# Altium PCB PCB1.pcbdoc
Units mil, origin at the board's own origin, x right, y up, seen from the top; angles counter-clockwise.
Board outline 2908.74 x 1290 mil, 4 copper layers (Top Layer, Inner1, Inner2, Bottom Layer); 41 components, 33 nets, 166 pads, 81 vias.
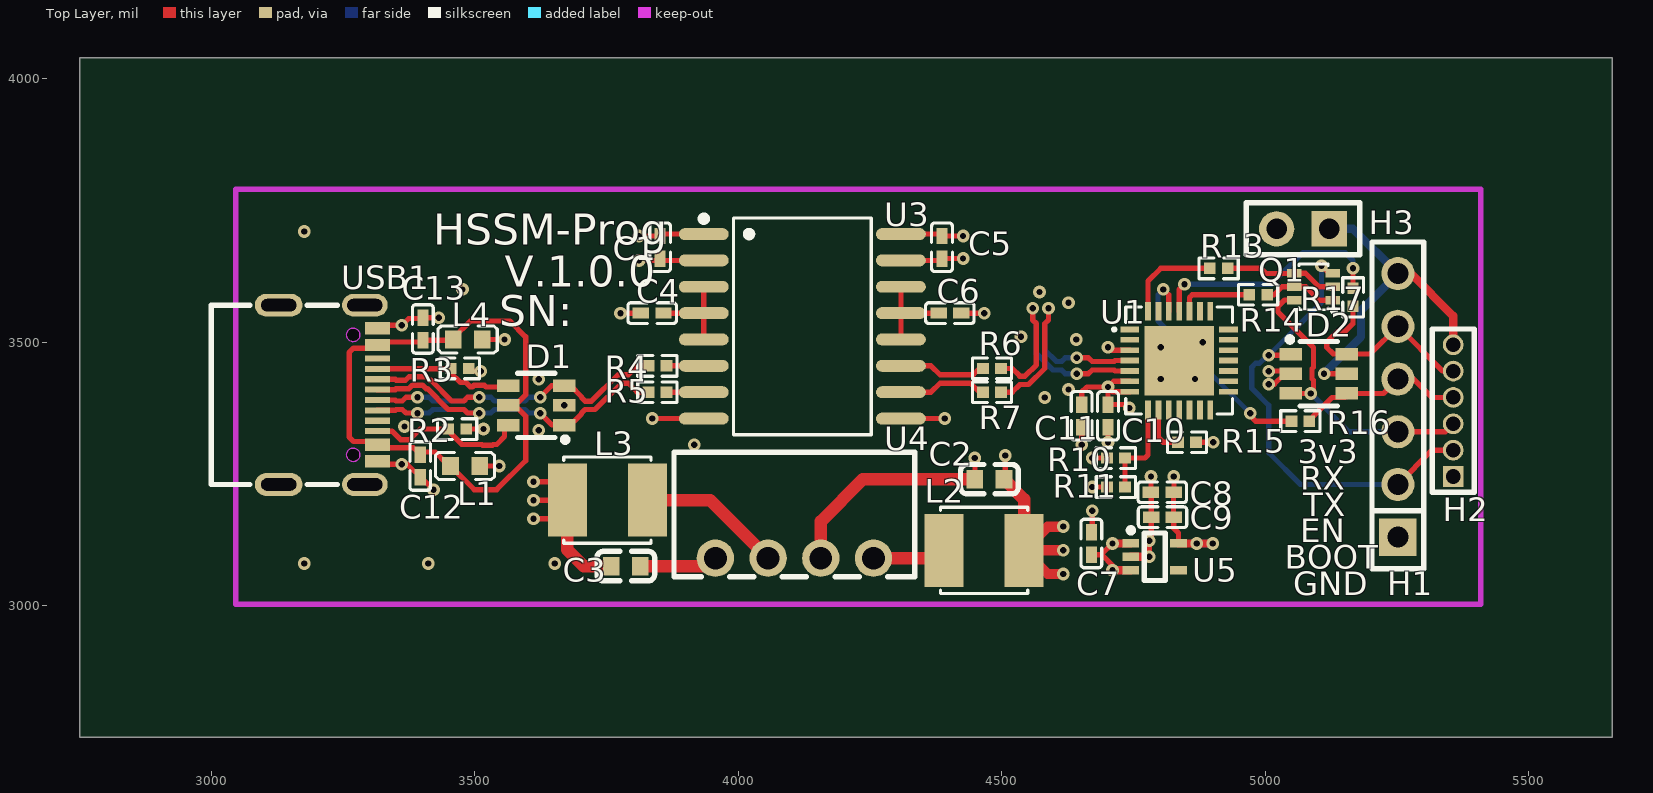
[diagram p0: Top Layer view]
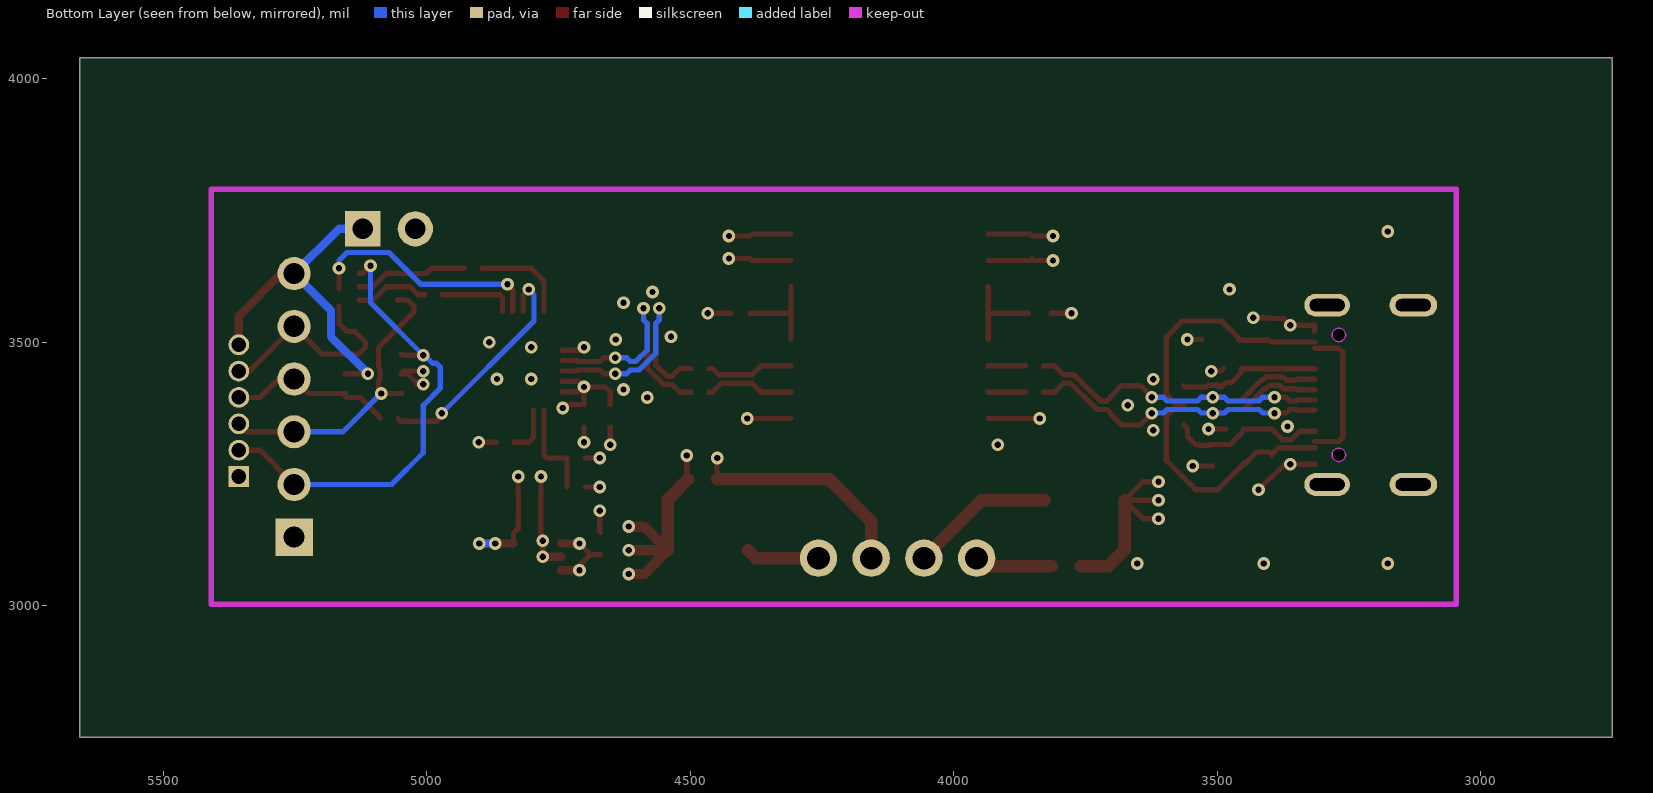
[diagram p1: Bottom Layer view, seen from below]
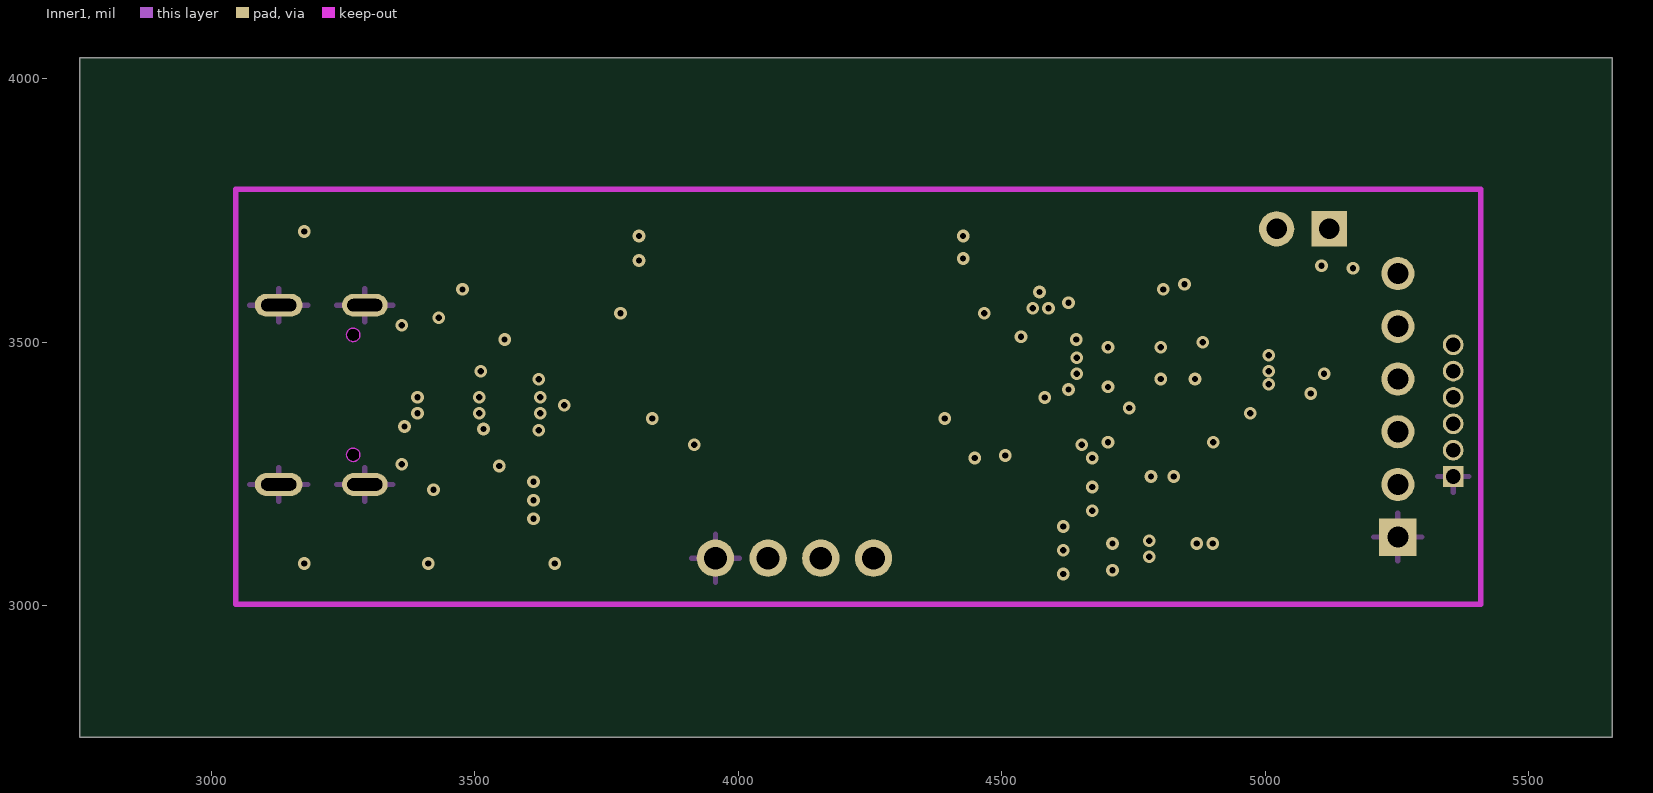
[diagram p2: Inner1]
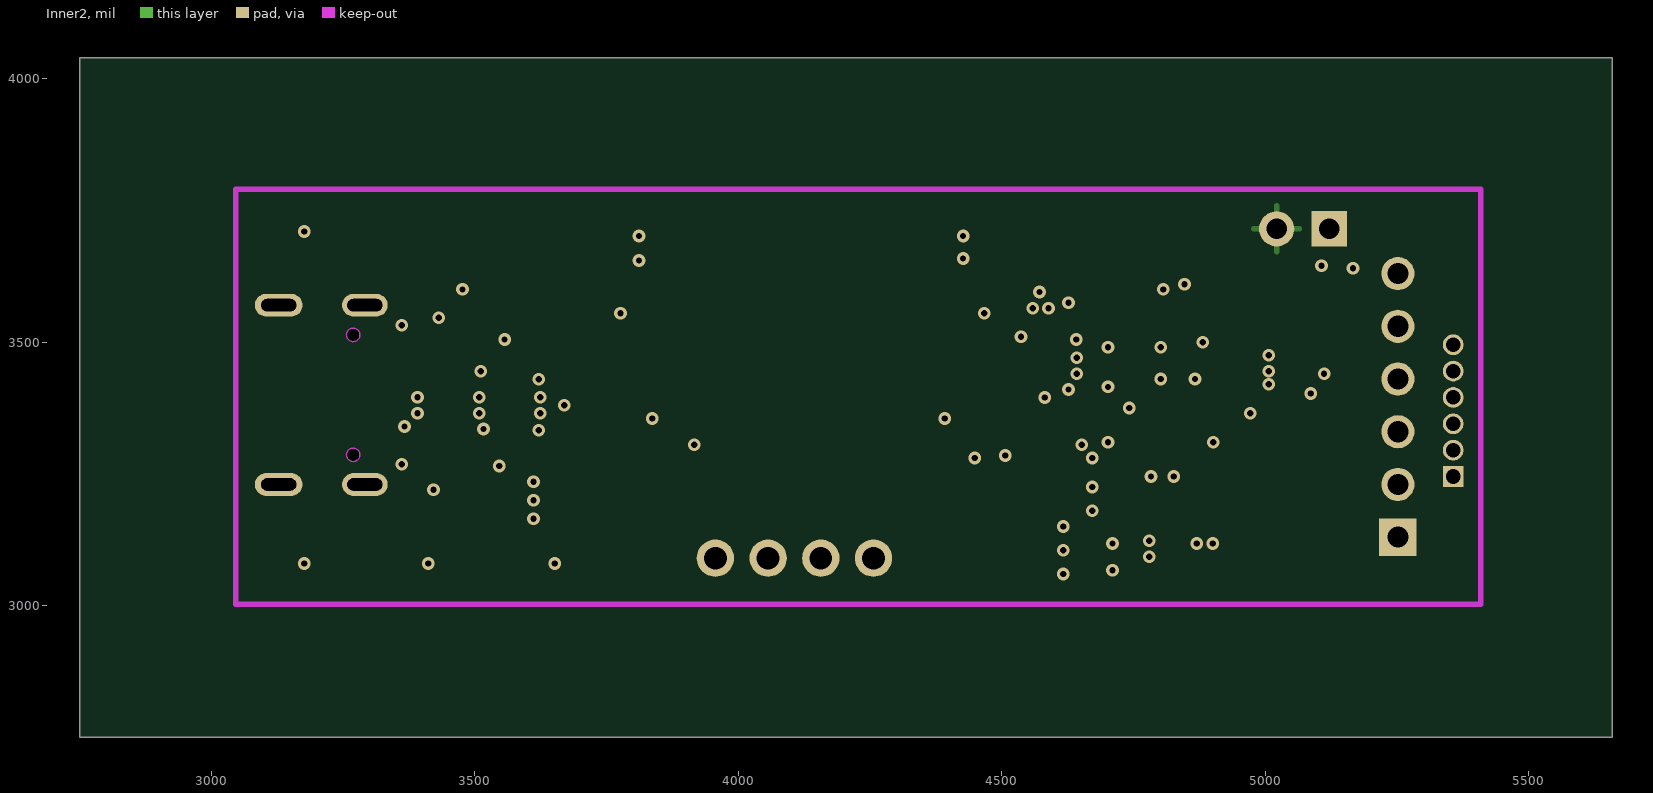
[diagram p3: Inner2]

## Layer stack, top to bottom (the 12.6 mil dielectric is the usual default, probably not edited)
Top Layer: signal copper (thickness not stored)
Dielectric: dielectric 12.6, FR-4, Dk 4.8
Inner1: signal copper (thickness not stored)
Dielectric: dielectric 12.6, FR-4, Dk 4.8
Inner2: signal copper (thickness not stored)
Dielectric: dielectric 12.6, FR-4, Dk 4.8
Bottom Layer: signal copper (thickness not stored)

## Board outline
5658.74,2750 2750,2750 2750,4040 5658.74,4040

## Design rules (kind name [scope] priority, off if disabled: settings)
BoardOutlineClearance copperThickness1oz [All] p0: genericclearance=10 ignorepadtopadclearanceinfootprint=FALSE except(0: Arc-SplitContinuation Track-SplitContinuation SMDPad-SplitContinuation THPad-SplitContinuation Via-SplitContinuation Fill-SplitContinuation Poly-SplitContinuation Region-SplitContinuation Text-SplitContinuation; 6: Track-CutoutEdge SMDPad-CutoutEdge THPad-CutoutEdge Via-CutoutEdge Region-CutoutEdge; 11.8: Track-OutlineEdge SMDPad-OutlineEdge THPad-OutlineEdge Via-OutlineEdge Fill-OutlineEdge Region-OutlineEdge Poly-OutlineEdge Text-OutlineEdge Fill-CutoutEdge)
BoardOutlineClearance copperThickness2oz [All] p0: genericclearance=10 ignorepadtopadclearanceinfootprint=FALSE except(0: Arc-SplitContinuation Track-SplitContinuation SMDPad-SplitContinuation THPad-SplitContinuation Via-SplitContinuation Fill-SplitContinuation Poly-SplitContinuation Region-SplitContinuation Text-SplitContinuation; 6: Track-CutoutEdge SMDPad-CutoutEdge THPad-CutoutEdge Via-CutoutEdge Region-CutoutEdge; 11.8: Track-OutlineEdge SMDPad-OutlineEdge THPad-OutlineEdge Via-OutlineEdge Fill-OutlineEdge Region-OutlineEdge Poly-OutlineEdge Text-OutlineEdge Fill-CutoutEdge)
Clearance copperThickness1oz [(InNet('VBUS') OR InNet('GND') OR InNet('ISOVBUS') OR InNet('ISOGND') OR InNet('VDD') OR InNet('ISOVDD') OR InNet('ISO3V3') OR InNet('USB_DN') OR InNet('USB_DP') OR InNet('CC2') OR InNet('CC1') OR InNet('ISO_EN') OR InNet('ISO_BOOT') OR InNet('ISO_RX') OR InNet('ISO_TX') OR InNet('$1N3534') OR InNet('$1N3529') OR InNet('DTR') OR InNet('RTS') OR InNet('ISO_USB_DN') OR InNet('ISO_USB_DP') OR InNet('$1N4589') OR InNet('$1N5325') OR InNet('$1N5370') OR InNet('$1N4087') OR InNet('$1N8654') OR InNet('$1N8663') OR InNet('VBUS_CONN') OR InNet('USB_DN_IC') OR InNet('USB_DP_IC') OR InNet('ISO_USB_DN_IC') OR InNet('ISO_USB_DP_IC') OR InNet('3V3_OUT'))] p1: gap=7 ignorepadtopadclearanceinfootprint=FALSE except(4: Track-Track; 6: Track-SMDPad SMDPad-SMDPad Track-THPad SMDPad-THPad THPad-THPad Track-Via SMDPad-Via THPad-Via Via-Via SMDPad-Fill THPad-Fill Via-Fill Fill-Fill Track-Region SMDPad-Region THPad-Region Via-Region Region-Region Track-Poly SMDPad-Poly THPad-Poly Via-Poly Fill-Poly Region-Poly Poly-Poly Track-Text SMDPad-Text THPad-Text Via-Text Fill-Text Region-Text Poly-Text Text-Text; 6.9: Track-Hole SMDPad-Hole THPad-Hole Via-Hole Fill-Hole Region-Hole Poly-Hole Text-Hole Sheet-Hole; 11.8: Track-Fill Fill-Region Track-Sheet SMDPad-Sheet THPad-Sheet Via-Sheet Fill-Sheet Region-Sheet Poly-Sheet Text-Sheet)
Clearance copperThickness2oz [All] p1: gap=7 ignorepadtopadclearanceinfootprint=FALSE except(6: Track-SMDPad SMDPad-SMDPad Track-THPad SMDPad-THPad THPad-THPad Track-Via SMDPad-Via THPad-Via Via-Via SMDPad-Fill THPad-Fill Via-Fill Fill-Fill Track-Region SMDPad-Region THPad-Region Via-Region Region-Region Track-Poly SMDPad-Poly THPad-Poly Via-Poly Fill-Poly Region-Poly Poly-Poly Track-Text SMDPad-Text THPad-Text Via-Text Fill-Text Region-Text Poly-Text Text-Text; 6.9: Track-Hole SMDPad-Hole THPad-Hole Via-Hole Fill-Hole Region-Hole Poly-Hole Text-Hole Sheet-Hole; 8: Track-Track; 11.8: Track-Fill Fill-Region Track-Sheet SMDPad-Sheet THPad-Sheet Via-Sheet Fill-Sheet Region-Sheet Poly-Sheet Text-Sheet)
DiffPairsRouting differentialPair [All] p1: maxuncoupledlength=10 minlimit=5.9843 maxlimit=5.9843 mostfreqgap=5.9843 toplayer_minwidth=5 toplayer_prefwidth=10 toplayer_maxwidth=100 bottomlayer_minwidth=5 bottomlayer_prefwidth=10 bottomlayer_maxwidth=100 midlayer1_minwidth=5 midlayer1_prefwidth=10 midlayer1_maxwidth=100 midlayer2_minwidth=5 midlayer2_prefwidth=10 midlayer2_maxwidth=100
PasteMaskExpansion pasteMaskExpansion [All] p1: expansion=0
PlaneConnect innerPlane [All] p1: planeconnectstyle=Relief reliefexpansion=20 reliefentries=4 reliefconductorwidth=10 reliefairgap=10
PolygonConnect copperRegion [All] p1: connectstyle=Relief reliefentries=4 reliefconductorwidth=10 polygonreliefangle="90 Angle" airgapwidth=10
RoutingVias viaSize [All] p1: viastyle="Through Hole" holewidth=12.0078 minholewidth=11.811 maxholewidth=248.0314 width=24.0158 minwidth=19.685 maxwidth=393.7008
SolderMaskExpansion solderMaskExpansion [All] p1: useseparateexpansions=TRUE expansion=2.0079 expansionbottom=2.0079
Width copperThickness1oz [All] p1: maxlimit=100 minlimit=5 preferedwidth=10
Width copperThickness2oz [All] p1: maxlimit=100 minlimit=8 preferedwidth=10

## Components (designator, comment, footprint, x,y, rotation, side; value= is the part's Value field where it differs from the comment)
C1 "" C0402 3851.54,3680 r90 top
C2 "" C0603 4476.54,3240 r0 top
C3 "" C0603 3786.54,3075 r180 top
C4 "" C0402 3836.54,3555 r0 top
C5 "" C0402 4386.54,3680 r90 top
C6 "" C0402 4401.54,3555 r180 top
C7 "" C0402 4670.04,3117.88 r270 top
C8 "" C0402 4804.46,3215 r0 top
C9 "" C0402 4805.04,3167.88 r0 top
C10 "" C0402 4701.54,3360 r90 top
C11 "" C0402 4651.54,3360 r90 top
C12 "" C0402 3396.54,3265 r90 top
C13 "" C0402 3401.54,3525 r270 top
D1 "" SOT-23-6_L2.9-W1.6-P0.95-LS2.8-BR 3616.54,3380 r0 top
D2 "" SOT-23-6_L2.9-W1.6-P0.95-LS2.8-BR 5101.54,3440 r180 top
H1 "" HDR-TH_6P-P2.54-V-F 5251.54,3380 r90 top
H2 "" HDR-TH_6P-P1.27-V-M-A 5356.54,3370 r90 top
H3 "" HDR-TH_2P-P2.54-V-F 5071.54,3715 r180 top
L1 "" L0603 3481.54,3265 r0 top
L2 "" IND-SMD_L4.0-W4.0_SMNR4020 4466.54,3105 r0 top
L3 "" IND-SMD_L4.0-W4.0_SMNR4020 3751.54,3200 r0 top
L4 "" L0603 3486.54,3505 r0 top
Q1 "" SOT-363_L2.0-W1.3-P0.65-LS2.1-TL 5091.54,3605 r180 top
R2 "" R0402 3466.54,3335 r180 top
R3 "" R0402 3471.54,3450 r180 top
R4 "" R0402 3846.54,3455 r0 top
R5 "" R0402 3846.54,3405 r0 top
R6 "" R0402 4481.54,3450 r0 top
R7 "" R0402 4481.54,3405 r0 top
R10 "" R0402 4716.54,3280 r180 top
R11 "" R0402 4716.54,3225 r0 top
R13 "" R0402 4911.54,3640 r180 top
R14 "" R0402 4986.54,3590 r180 top
R15 "" R0402 4851.54,3310 r180 top
R16 "" R0402 5066.54,3350 r0 top
R17 "" R0402 5166.54,3585 r270 top
U1 "" QFN-28_L5.0-W5.0-P0.50-TL-EP3.3 4836.54,3465 r0 top
U3 "" SOIC-16_L10.3-W7.5-P1.27-LS10.3-BL 4121.54,3530 r270 top
U4 "" PWRM-TH_HLK-1DXXXX 4106.54,3090 r180 top
U5 "" SOT-353_L2.1-W1.3-P0.65-LS2.3-BL 4790.04,3092.88 r270 top
USB1 "" USB-C_UC09-0B16F00P11 3221.54,3400 r270 top

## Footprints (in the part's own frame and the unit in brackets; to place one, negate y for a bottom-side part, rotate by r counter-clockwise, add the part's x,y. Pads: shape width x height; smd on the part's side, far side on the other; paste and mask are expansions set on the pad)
C0402 [mm]
  rect 0.79x0.54 smd: 1(-0.545,0) 2(0.545,0)
  silkscreen extent -1.17,-0.5 1.17,0.5
C0603 [mm]
  rect 0.8x0.9 smd: 1(-0.7,0) 2(0.7,0)
  silkscreen extent -1.39,-0.71 1.39,0.71
HDR-TH_2P-P2.54-V-F [mm]
  rect 1.7x1.7 hole 1: 1(-1.27,0)
  round 1.7 hole 1: 2(1.27,0)
  silkscreen extent -2.74,-1.25 2.74,1.25
HDR-TH_6P-P1.27-V-M-A [mm]
  rect 1x1 hole 0.7: 1(-3.175,0)
  round 1 hole 0.7: 2(-1.905,0) 3(-0.635,0) 4(0.635,0) 5(1.905,0) 6(3.175,0)
  silkscreen extent -3.94,-1.02 3.94,1.02
HDR-TH_6P-P2.54-V-F [mm]
  rect 1.8x1.8 hole 1.02: 1(-6.35,0)
  round 1.6 hole 1.02: 2(-3.81,0) 3(-1.27,0) 4(1.27,0) 5(3.81,0) 6(6.35,0)
  silkscreen extent -7.87,-1.25 7.87,1.25
IND-SMD_L4.0-W4.0_SMNR4020 [mm]
  rect 1.874x3.52 smd: 1(1.928,0) 2(-1.928,0)
  silkscreen extent -2.1,-2.08 2.1,2.08
L0603 [mm]
  rect 0.8x0.864 smd: 1(-0.7,0) 2(0.7,0)
  silkscreen extent -1.42,-0.65 1.42,0.65
PWRM-TH_HLK-1DXXXX [mm]
  round 1.8 hole 1.1: 1(3.81,0) 2(1.27,0) 3(-1.27,0) 4(-3.81,0)
  silkscreen extent -5.8,-5.1 5.8,0.9
QFN-28_L5.0-W5.0-P0.50-TL-EP3.3 [mm]
  rect 0.905x0.28 smd: 1(-2.377,1.5) 2(-2.377,1) 3(-2.377,0.5) 4(-2.377,0) 5(-2.377,-0.5) 6(-2.377,-1) 7(-2.377,-1.5) 15(2.377,-1.5) 16(2.377,-1) 17(2.377,-0.5) 18(2.377,0) 19(2.377,0.5) 20(2.377,1) 21(2.377,1.5)
  rect 0.28x0.905 smd: 8(-1.5,-2.377) 9(-1,-2.377) 10(-0.5,-2.377) 11(0,-2.377) 12(0.5,-2.377) 13(1,-2.377) 14(1.5,-2.377) 22(1.5,2.377) 23(1,2.377) 24(0.5,2.377) 25(0,2.377) 26(-0.5,2.377) 27(-1,2.377) 28(-1.5,2.377)
  rect 3.35x3.35 smd: 29(0,0)
  silkscreen extent -3.2,-2.58 2.58,2.58
R0402 [mm]
  rect 0.566x0.54 smd: 1(-0.433,0) 2(0.433,0)
  silkscreen extent -0.94,-0.5 0.94,0.5
SOIC-16_L10.3-W7.5-P1.27-LS10.3-BL [mil]
  oval 22.6x94.51 smd: 1(-175,-187.02) 2(-125,-187.02) 3(-75,-187.02) 4(-25,-187.02) 5(25,-187.02) 6(75,-187.02) 7(125,-187.02) 8(175,-187.02) 9(175,187.02) 10(125,187.02) 11(75,187.02) 12(25,187.02) 13(-25,187.02) 14(-75,187.02) 15(-125,187.02) 16(-175,187.02)
  silkscreen extent -210,-193 206,131
SOT-23-6_L2.9-W1.6-P0.95-LS2.8-BR [mm]
  rect 1.1x0.6 smd: 1(1.35,-0.95) 2(1.35,0) 3(1.35,0.95) 4(-1.35,0.95) 5(-1.35,0) 6(-1.35,-0.95)
  silkscreen extent -0.9,-1.78 1.52,1.55
SOT-353_L2.1-W1.3-P0.65-LS2.3-BL [mm]
  rect 0.4x0.8 smd: 1(-0.65,-1.15) 2(0,-1.15) 3(0.65,-1.15) 4(0.65,1.15) 5(-0.65,1.15)
  silkscreen extent -1.4,-1.27 1.14,0.51
SOT-363_L2.0-W1.3-P0.65-LS2.1-TL [mm]
  rect 0.7x0.42 smd: 1(-0.92,0.65) 2(-0.92,0) 3(-0.92,-0.65) 4(0.92,-0.65) 5(0.92,0) 6(0.92,0.65)
  silkscreen extent -1.09,-1.1 0.7,1.24
USB-C_UC09-0B16F00P11 [mm]
  oval 1.1x2.2 hole 0.6 slot 1.7 at 90 deg: 17(4.32,1.772) 20(-4.32,1.772)
  oval 1.1x2.3 hole 0.6 slot 1.7 at 90 deg: 18(4.32,-2.377) 19(-4.32,-2.378)
  rect 0.3x1.21 smd: A1(-3.35,2.378) A4(-2.55,2.378) A5(-1.25,2.378) A6(-0.25,2.378) A7(0.25,2.378) A8(1.249,2.378) A9(2.55,2.378) A12(3.35,2.378) B1(3.05,2.378) B4(2.25,2.378) B5(1.75,2.378) B6(0.75,2.378) B7(-0.75,2.378) B8(-1.75,2.378) B9(-2.25,2.378) B12(-3.05,2.378)
  Board Outline Layer circle w0.005: c2.89,1.212 r0.325
  Board Outline Layer circle w0.005: c-2.89,1.212 r0.325
  Board Outline Layer region: 2.89,1.537 3.031,1.505 3.144,1.415 3.207,1.285 3.207,1.14 3.144,1.01 3.031,0.92 2.89,0.887 2.89,0.887 2.749,0.92 2.636,1.01 2.573,1.14 2.573,1.285 2.636,1.415 2.749,1.505 2.89,1.537
  Board Outline Layer region: -2.89,1.537 -2.749,1.505 -2.636,1.415 -2.573,1.285 -2.573,1.14 -2.636,1.01 -2.749,0.92 -2.89,0.887 -2.89,0.887 -3.031,0.92 -3.144,1.01 -3.207,1.14 -3.207,1.285 -3.144,1.415 -3.031,1.505 -2.89,1.537
  Multi-Layer board cut-out: 2.89,1.537 3.031,1.505 3.144,1.415 3.207,1.285 3.207,1.14 3.144,1.01 3.031,0.92 2.89,0.887 2.89,0.887 2.749,0.92 2.636,1.01 2.573,1.14 2.573,1.285 2.636,1.415 2.749,1.505 2.89,1.537
  Multi-Layer board cut-out: -2.89,1.537 -2.749,1.505 -2.636,1.415 -2.573,1.285 -2.573,1.14 -2.636,1.01 -2.749,0.92 -2.89,0.887 -2.89,0.887 -3.031,0.92 -3.144,1.01 -3.207,1.14 -3.207,1.285 -3.144,1.415 -3.031,1.505 -2.89,1.537
  silkscreen extent -4.32,-5.63 4.32,0.44

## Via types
v1: diameter 24.02, hole 12.01, Top Layer to Bottom Layer, 81 vias

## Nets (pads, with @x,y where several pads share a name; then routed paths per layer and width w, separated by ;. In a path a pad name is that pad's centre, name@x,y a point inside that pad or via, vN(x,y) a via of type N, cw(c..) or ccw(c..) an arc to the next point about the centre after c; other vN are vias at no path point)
3V3_OUT: D2.5 H1.6 H2.6 H3.1 | length 649.5
  Top Layer w10: v1(5111.54,3440) D2.5
  Top Layer w15.75: H1.6 5276.54,3630 5356.54,3550 H2.6
  Bottom Layer w15.75: v1(5111.54,3440) 5181.54,3510 5181.54,3560 H1.6 5166.54,3715 H3.1
$1N3529: L3.1 U4.2 | length 274.7
  Top Layer w23.62: L3.1 3946.53,3200 U4.2
$1N3534: L2.2 U4.4 | length 140.3
  Top Layer w23.62: U4.4 4375.62,3090 L2.2
$1N4087: R15.2 U1.9 | length 93.2
  Top Layer w10: U1.9 4797.17,3319.37 4806.54,3310 R15.2
$1N4589: R10.1 R11.2 U1.8 | length 186.8
  Top Layer w10: R11.2 R10.1 4771.54,3280 4777.49,3285.95 U1.8
$1N5325: R13.2 U1.28 | length 184.3
  Top Layer w10: U1.28 4777.49,3615.95 4801.54,3640 R13.2
$1N5370: R14.2 U1.24 | length 141.6
  Top Layer w10: U1.24 4856.23,3584.69 4861.54,3590 R14.2
$1N8654: R17.1 U1.25 | length 459.6
  Top Layer w10: U1.25 4836.54,3600 v1(4846.54,3610) ; R17.1 v1(5166.54,3640)
  Bottom Layer w10: v1(4846.54,3610) 5011.54,3610 5071.54,3670 5151.54,3670 5166.54,3655 v1(5166.54,3640)
$1N8663: R16.1 U1.26 | length 451.5
  Top Layer w10: v1(4806.54,3600) 4816.86,3589.68 U1.26 ; v1(4971.54,3365) 4971.54,3360 4981.54,3350 R16.1 R16.1@5054.5,3355
  Bottom Layer w10: v1(4806.54,3600) 4796.54,3590 4796.54,3540 v1(4971.54,3365)
CC1: D1.4 R3.2 USB1.A5 | length 265.5
  Top Layer w10: USB1.A5 R3.2@3448.71,3449.22 ; R3.2 3454.5,3441.78 3472.89,3423.39 3483.15,3423.39 3491.54,3415 3495.44,3415 3498.73,3418.28 3517.77,3418.28 3521.06,3415 3560.99,3415 D1.4
CC2: D1.6 R2.2 USB1.B5 | length 293
  Top Layer w10: USB1.B5 3342.91,3331.11 3359.02,3315 3376.54,3315 3396.54,3335 R2.2 ; R2.2@3453.78,3327.5 3475.39,3305.89 3513.13,3305.89 3514.51,3304.51 3533.56,3304.51 3534.94,3305.89 3541.67,3305.89 3556.54,3320.75 3556.54,3335.75 D1.6
DTR: Q1.2 Q1.4 R13.1 | length 214.2
  Top Layer w10: R13.1 4991.54,3640 5001.54,3630 5054.73,3630 Q1.4 5075.95,3630.59 5101.54,3605 Q1.2
GND: C1.1 C3.1 C4.1 C12.1 C13.1 D1.2 R2.1 R3.1 U3.2 U3.8 U4.1 USB1.17 USB1.18 USB1.19 USB1.20 USB1.A1 USB1.A12 USB1.B1 USB1.B12 | length 729.6
  Top Layer w10: USB1.A12 v1(3361.54,3268.12) 3371.96,3268.12 C12.1 3398,3243.54 v1(3421.54,3220) ; USB1.B12 USB1.A1 v1(3361.54,3531.9) 3374.64,3545 3400.08,3545 C13.1 v1(3431.54,3546.46) ; R2.1 v1(3516.54,3335) ; R3.1 3493.58,3445 v1(3511.54,3445) ; v1(3776.54,3555) C4.1 ; v1(3811.54,3655) 3848,3655 C1.1 3855.08,3655 U3.2 ; v1(3836.54,3355) U3.8
  Top Layer w23.62: C3.1 3941.54,3075 U4.1
  other v1: 3176.54,3080 3411.54,3080 3651.54,3080 3916.54,3305 3621.54,3332.54 3366.54,3340 3669.69,3380 3621.54,3429.51 3476.54,3600 3176.54,3710
ISO3V3: C8.2 C9.2 C10.2 C11.2 H3.2 R15.1 U1.6 U1.7 U5.5 | length 498.5
  Top Layer w10: C11.2 4651.54,3405 4661.54,3415 v1(4701.54,3415) ; v1(4741.54,3375) 4735.08,3381.46 C10.2 v1(4701.54,3415) ; U1.7 4710.6,3405.94 v1(4701.54,3415) ; U1.6 4712.17,3425.63 v1(4701.54,3415) ; C9.2@4826.5,3162.88 4826.5,3146.42 4835.31,3137.6 U5.5 ; C9.2 4825.92,3168.46 C8.2 4826.54,3215.62 v1(4826.54,3245) ; R15.1 v1(4901.54,3310)
  Top Layer w15.75: U5.5 4835.9,3117.88 v1(4870.04,3117.88) v1(4900.04,3117.88)
  Bottom Layer w15.75: v1(4870.04,3117.88) v1(4900.04,3117.88)
ISO_BOOT: D2.1 H1.2 H2.2 Q1.3 | length 900.7
  Top Layer w10: v1(5006.54,3475) 5045.99,3475 D2.1 ; v1(5106.54,3645) 5120.95,3630.59 Q1.3 ; H1.2 5316.54,3295 H2.2
  Bottom Layer w10: v1(5106.54,3645) 5106.54,3575 v1(5006.54,3475) 4999.53,3467.99 4997.01,3467.99 4989.02,3460 4981.54,3460 4974.46,3452.93 4974.46,3412.07 5006.54,3380 5006.54,3290 5066.54,3230 H1.2
ISO_EN: D2.3 H1.3 H2.3 Q1.6 | length 578.5
  Top Layer w10: D2.3 v1(5086.54,3402.6) 5091.54,3407.6 5091.54,3427.48 5088.54,3430.48 5088.54,3449.52 5091.54,3452.52 5091.54,3490 5024.04,3557.5 5024.04,3567.5 5036.54,3580 5054.73,3580 Q1.6 ; H1.3 5341.54,3330 H2.3
  Bottom Layer w10: v1(5086.54,3402.6) 5159.14,3330 H1.3
ISO_RX: D2.6 H1.5 H2.5 R17.2 | length 409.7
  Top Layer w10: R17.2 5166.54,3535 5151.54,3520 5136.54,3520 5116.54,3500 5116.54,3490 5129.14,3477.4 D2.6 5198.94,3477.4 H1.5 5336.54,3445 H2.5
ISO_TX: D2.4 H1.4 H2.4 R16.2 | length 317.6
  Top Layer w10: R16.2@5088.58,3355 5088.58,3357.04 5126.54,3395 5152.09,3395 5154.69,3397.6 D2.4 5224.14,3402.6 H1.4 5281.54,3430 5316.54,3395 H2.4
ISO_USB_DN: R6.2 U1.5 | length 477.3
  Top Layer w10: R6.2 4519.71,3450 4534.22,3435.49 4544.22,3435.49 4565.55,3456.82 4565.55,3535 4558.54,3542.01 v1(4558.54,3564.02) ; v1(4642.52,3440.16) 4664.53,3440.16 4671.54,3447.16 4713.27,3447.16 4715.12,3445.31 U1.5
  Bottom Layer w10: v1(4558.54,3564.02) 4558.54,3542.01 4565.55,3535 4565.55,3478.49 4596.88,3447.16 4613.5,3447.16 4620.51,3440.16 v1(4642.52,3440.16)
ISO_USB_DN_IC: R6.1 U3.11 | length 168
  Top Layer w10: U3.11 4365.81,3455 4382.82,3437.99 4445.87,3437.99 4457.88,3450 R6.1
ISO_USB_DP: R7.2 U1.4 | length 477.3
  Top Layer w10: R7.2 4519.71,3405 4534.22,3419.51 4550.84,3419.51 4581.54,3450.2 4581.54,3535 4588.54,3542.01 v1(4588.54,3564.02) ; v1(4642.52,3470.16) 4664.53,3470.16 4671.54,3463.15 4713.27,3463.15 4715.12,3465 U1.4
  Bottom Layer w10: v1(4588.54,3564.02) 4588.54,3542.01 4581.54,3535 4581.54,3485.12 4603.5,3463.15 4613.5,3463.15 4620.51,3470.16 v1(4642.52,3470.16)
ISO_USB_DP_IC: R7.1 U3.10 | length 170
  Top Layer w10: U3.10 4365.81,3405 4382.82,3422.01 4440.87,3422.01 4457.88,3405 R7.1
ISOGND: C2.1 C5.1 C6.1 C7.1 C8.1 C9.1 C10.1 C11.1 D2.2 H1.1 H2.1 R11.1 U1.3 U1.29 U3.9 U3.15 U4.3 U5.2 | length 1134.6
  Top Layer w10: U3.9 v1(4391.54,3355) ; U3.15 4383,3655 C5.1 v1(4426.54,3658.54) ; C6.1 v1(4466.54,3555) ; C2.1 v1(4448.98,3280) ; v1(4651.54,3305) C11.1 ; C7.1 4671.54,3140.84 v1(4671.54,3180) ; v1(4671.54,3225) R11.1 ; v1(4701.54,3310) C10.1 ; v1(4701.54,3490) 4706.86,3484.68 U1.3 ; v1(4780.04,3092.88) v1(4780.04,3122.88) 4783.58,3126.42 C9.1@4783.58,3162.88 ; v1(4783,3245) C8.1 4783.58,3214.42 C9.1 ; v1(5006.54,3420) 5016.79,3420 5036.79,3440 D2.2 5043.39,3445 v1(5006.54,3445)
  Top Layer w15.75: U5.2 v1(4780.04,3092.88)
  Top Layer w23.62: U4.3 4156.54,3160 4236.54,3240 C2.1
  other v1: 4581.54,3395 4626.54,3410 4801.54,3430 4866.54,3430 4801.54,3490 4881.54,3500 4641.54,3505 4536.54,3510 4626.54,3575 4571.54,3595
ISOVBUS: C2.2 C5.2 C7.2 L2.1 R10.2 U3.16 U5.1 U5.3 | length 761.3
  Top Layer w10: U3.16 4383,3705 C5.2 v1(4426.54,3701.46) ; C2.2 4506.54,3242.44 v1(4506.54,3285) ; C7.2 4688.58,3096.42 ; v1(4671.54,3280) R10.2 ; v1(4710.04,3067.29) 4710.04,3076.4 4690.02,3096.42 4688.58,3096.42 ; v1(4710.04,3117.88) 4688.58,3096.42
  Top Layer w15.75: v1(4710.04,3067.29) U5.3 ; v1(4710.04,3117.88) 4744.17,3117.88 U5.1
  Top Layer w19.68: v1(4616.54,3060) 4587.45,3060 L2.1 ; v1(4616.54,3105) L2.1 ; v1(4616.54,3150) 4587.45,3150 L2.1
  Top Layer w23.62: C2.2 4542.45,3201.65 L2.1
ISOVDD: C6.2 U3.12 U3.13 U3.14 | length 178.6
  Top Layer w10: U3.12 U3.13 ; U3.14 U3.13 ; C6.2@4386.54,3553.54 4385.08,3555 U3.13
RTS: Q1.1 Q1.5 R14.1 | length 141
  Top Layer w10: R14.1 5016.54,3590 5031.54,3605 Q1.5 5076.54,3605 5102.13,3579.41 Q1.1
USB_DN: D1.3 R4.1 USB1.A7 USB1.B7 | length 798.3
  Top Layer w10: USB1.A7 3348.96,3390.17 3350.81,3388.32 3362.36,3388.32 3369.37,3395.32 v1(3391.38,3395.32) ; USB1.B7 3348.96,3429.54 3350.81,3427.69 3368.62,3427.69 3375.23,3434.3 3407.52,3434.3 3414.14,3427.69 3416.68,3427.69 3456.08,3388.28 3479.23,3388.28 3486.24,3395.29 v1(3508.25,3395.29) ; v1(3624.03,3395.29) 3646.14,3417.4 D1.3 3681.28,3417.4 3702.32,3396.36 3702.32,3394.76 3709.09,3387.99 3721.54,3387.99 3771.54,3437.99 3791.35,3437.99 3808.36,3455 R4.1
  Bottom Layer w10: v1(3391.38,3395.32) 3413.39,3395.32 3420.4,3388.32 3479.23,3388.28 3486.24,3395.29 v1(3508.25,3395.29) 3530.26,3395.29 3537.27,3388.28 3595.01,3388.28 3602.02,3395.29 v1(3624.03,3395.29)
USB_DN_IC: R4.2 U3.6 | length 70.9
  Top Layer w10: R4.2 U3.6
USB_DP: D1.1 R5.1 USB1.A6 USB1.B6 | length 798.5
  Top Layer w10: USB1.B6 3348.96,3370.48 3350.81,3372.33 3362.36,3372.33 3369.37,3365.32 v1(3391.38,3365.32) ; USB1.A6 3348.96,3409.85 3350.81,3411.7 3375.24,3411.7 3381.86,3418.32 3400.9,3418.32 3407.52,3411.7 3410.06,3411.7 3449.46,3372.3 3479.23,3372.3 3486.24,3365.29 v1(3508.25,3365.29) ; v1(3624.03,3365.29) 3646.72,3342.6 D1.1 3681.28,3342.6 3702.32,3363.64 3702.32,3365.24 3709.09,3372.01 3728.16,3372.01 3778.16,3422.01 3791.35,3422.01 3808.36,3405 R5.1
  Bottom Layer w10: v1(3391.38,3365.32) 3413.39,3365.32 3420.4,3372.33 3479.23,3372.3 3486.24,3365.29 v1(3508.25,3365.29) 3530.26,3365.29 3537.27,3372.3 3595.01,3372.3 3602.02,3365.29 v1(3624.03,3365.29)
USB_DP_IC: R5.2 U3.7 | length 70.9
  Top Layer w10: R5.2 U3.7
VBUS: C1.2 C3.2 L1.2 L3.2 L4.2 U3.1 | length 600.8
  Top Layer w10: L1.2 v1(3546.54,3265) ; L4.2@3529.09,3505 v1(3556.54,3505) ; v1(3611.54,3165) 3640.63,3165 L3.2 ; v1(3611.54,3200) L3.2 ; v1(3611.54,3235) 3640.63,3235 L3.2 ; v1(3811.54,3701.46) C1.2 3855.08,3705 U3.1
  Top Layer w23.62: L3.2 3675.63,3105.91 3706.54,3075 C3.2
VBUS_CONN: C12.2 C13.2 D1.5 L1.1 L4.1 USB1.A4 USB1.A9 USB1.B4 USB1.B9 | length 1192
  Top Layer w10: USB1.A9 3383.39,3299.61 C12.2 3401.54,3291.46 3425.08,3291.46 3446.54,3270 3448.98,3270 L1.1 3498.98,3220 3541.54,3220 3596.54,3275 3596.54,3360 D1.5@3576.54,3380 ; USB1.B4 3270.11,3311.43 3261.54,3320 3261.54,3480 3270.12,3488.59 USB1.B9 ; USB1.A4 3398.39,3500.4 C13.2 3457.52,3503.54 L4.1 3458.98,3507.45 3491.54,3540 3566.54,3540 3596.54,3510 3596.54,3400 D1.5@3576.54,3380 ; D1.5 D1.5@3576.54,3380
VDD: C4.2 U3.3 U3.4 U3.5 | length 176.5
  Top Layer w10: C4.2 U3.4 ; U3.5 U3.4 ; U3.3 U3.4
pads on no net: U1.1 U1.2 U1.10 U1.11 U1.12 U1.13 U1.14 U1.15 U1.16 U1.17 U1.18 U1.19 U1.20 U1.21 U1.22 U1.23 U1.27 U5.4 USB1.A8 USB1.B8

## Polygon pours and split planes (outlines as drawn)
VBUS on Inner2 (solid, remove dead copper): 3046.54,3790 4023.29,3790 4023.29,3002.6 3046.54,3002.6
GND on Inner2 (solid, remove dead copper): 3336.54,3460 3686.54,3460 3686.54,3310 3336.54,3310
GND on Inner1 (solid, remove dead copper): 3046.54,3790 4026.43,3790 4026.43,3004.89 4021.54,3000 3051.54,3000 3046.54,3005
ISOGND on Inner1 (solid, remove dead copper): 4226.54,3790 4226.54,3000.08 5406.22,3000.08 5408.74,3002.6 5408.74,3790
ISOVBUS on Inner2 (solid, remove dead copper): 4227.64,3002.6 4803.94,3002.6 4806.54,3000 4806.54,3295 4576.54,3295 4516.54,3355 4516.54,3790 4226.54,3790 4226.54,3107.6
ISO3V3 on Inner2 (solid, remove dead copper): 4527.03,3254.51 4561.54,3220 4806.54,3220 4811.54,3215 4811.54,3002.6 5408.74,3002.6 5408.74,3790 4531.54,3790 4531.54,3609.49 4717.65,3609.49 4717.65,3447.97 4648.58,3378.9 4527.03,3378.9
ISOGND on Inner2 (solid, remove dead copper): 4717.65,3610 4521.54,3610 4521.54,3381.46 4651.54,3381.46 4715.12,3445.05 4715.12,3445.31 4717.65,3447.84

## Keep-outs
Board Outline Layer:
  lines w10: 3046.54,3002.6 5408.74,3002.6 5408.74,3790 3046.54,3790 3046.54,3002.6

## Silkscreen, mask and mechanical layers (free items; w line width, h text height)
Top Silkscreen Layer:
  text "HSSM-Prog" at 3421.54,3685 h59.06
  text "V.1.0.0" at 3556.54,3605 h59.06
  text "SN:" at 3546.54,3530 h59.06
  text "3v3" at 5061.54,3270 h45
  text "RX" at 5066.54,3220 h45
  text "TX" at 5071.54,3170 h45
  text "EN" at 5066.54,3120 h45
  text "BOOT" at 5036.54,3070 h45
  text "GND" at 5052.72,3019.84 h45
